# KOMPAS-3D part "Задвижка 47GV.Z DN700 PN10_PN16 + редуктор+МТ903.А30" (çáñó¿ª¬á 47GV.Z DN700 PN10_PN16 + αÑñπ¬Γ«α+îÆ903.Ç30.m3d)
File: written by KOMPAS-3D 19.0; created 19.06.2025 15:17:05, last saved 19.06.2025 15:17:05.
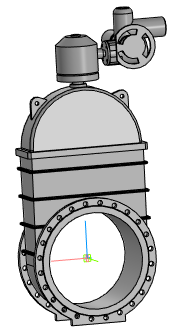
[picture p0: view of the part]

Document properties: Полное имя файла: Задвижка 47GV.Z DN700 PN10_PN16 + редуктор+МТ903.А30.a3d

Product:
- Part/product: Задвижка 47GV.Z DN700 PN10_PN16 + редуктор+МТ903.А30
    Масса: 2258.8

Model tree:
1. Операция без истории:1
